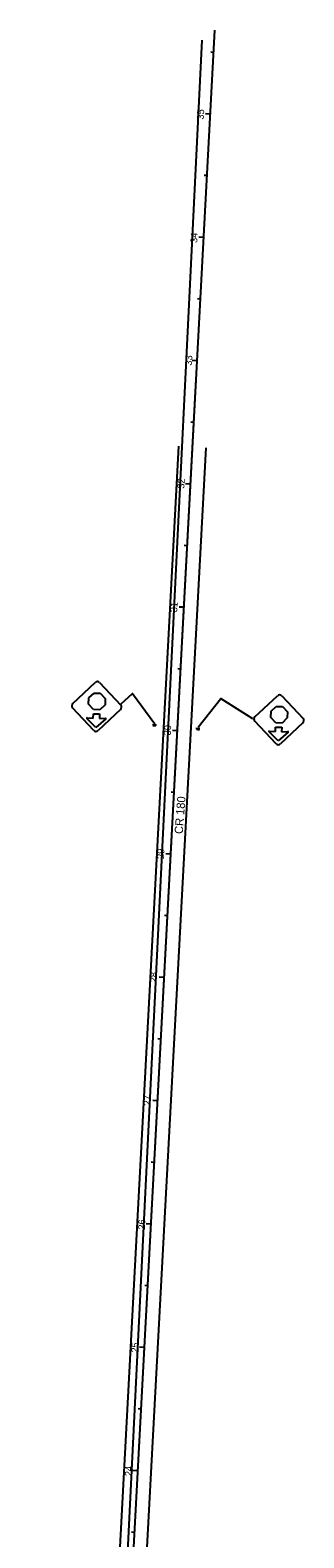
# Model space of a CAD drawing. Extents: x 1658454 to 1663955, y 480219 to 484109.
# Drawn here: x 1661328 to 1661550, y 482888 to 484109 of the extents above; entities that cross this region are included whole.
import ezdxf

# ---------------------------------------------------------------- set-up
doc = ezdxf.new("R2010")
doc.units = 0
for name, color, linetype in [('Default', 7, 'Continuous'), ('PM_P_CL_Double_Solid', 7, 'Continuous'), ('PV_P_EOP', 7, 'Continuous'), ('RW_X_CL_50', 7, 'Continuous'), ('SC_Scratch1', 7, 'Continuous'), ('SN_X_Public', 7, 'Continuous'), ('SV_X_CL_Survey_50', 7, 'Continuous'), ('SV_X_Text', 7, 'Continuous')]:
    doc.layers.add(name, color=color, linetype=linetype)

msp = doc.modelspace()

# ---------------------------------------------------------------- linework, layer by layer
at = {"layer": 'Default'}
for p, q in [((1661476.7, 484091), (1661474.3, 484091.1)), ((1661474, 484041.1), (1661470.1, 484041.3)), ((1661471.4, 483991.2), (1661469, 483991.3)), ((1661468.7, 483941.2), (1661464.7, 483941.4)), ((1661466, 483891.3), (1661463.6, 483891.4)), ((1661463.4, 483841.4), (1661459.4, 483841.6)), ((1661460.7, 483791.4), (1661458.3, 483791.6)), ((1661458, 483741.5), (1661454, 483741.7)), ((1661455.3, 483691.6), (1661452.9, 483691.7)), ((1661452.7, 483641.7), (1661448.7, 483641.9)), ((1661450, 483591.7), (1661447.6, 483591.9)), ((1661447.3, 483541.8), (1661443.3, 483542)), ((1661444.7, 483491.9), (1661442.3, 483492)), ((1661442, 483441.9), (1661438, 483442.2)), ((1661439.3, 483392), (1661436.9, 483392.1)), ((1661436.6, 483342.1), (1661432.6, 483342.3)), ((1661434, 483292.2), (1661431.6, 483292.3)), ((1661431.3, 483242.2), (1661427.3, 483242.4)), ((1661428.6, 483192.3), (1661426.2, 483192.4)), ((1661426, 483142.4), (1661422, 483142.6)), ((1661423.3, 483092.4), (1661420.9, 483092.6)), ((1661420.6, 483042.5), (1661416.6, 483042.7)), ((1661417.9, 482992.6), (1661415.5, 482992.7)), ((1661415.3, 482942.7), (1661411.3, 482942.9)), ((1661412.6, 482892.7), (1661410.2, 482892.9))]:
    msp.add_line(p, q, dxfattribs=at)
at = {"layer": 'PM_P_CL_Double_Solid'}
msp.add_line((1661344.5, 481619.5), (1661462.6, 483826.4), dxfattribs=at)
at = {"layer": 'PV_P_EOP'}
for p, q in [((1661398.1, 482828.2), (1661448.6, 483772.1)), ((1661420.1, 482827.1), (1661470.6, 483770.9))]:
    msp.add_line(p, q, dxfattribs=at)
at = {"layer": 'RW_X_CL_50'}
msp.add_line((1661341.7, 481544.6), (1661467.4, 484100.9), dxfattribs=at)
at = {"layer": 'SC_Scratch1'}
for p, q in [((1661375.5, 483568.3), (1661379.9, 483572.3)), ((1661379.9, 483572.3), (1661384.8, 483572.1)), ((1661384.8, 483572.1), (1661388.9, 483567.9)), ((1661375.4, 483563.2), (1661375.5, 483568.3)), ((1661379.5, 483558.9), (1661375.4, 483563.2)), ((1661384.4, 483558.8), (1661379.5, 483558.9)), ((1661388.8, 483562.8), (1661384.4, 483558.8)), ((1661388.9, 483567.9), (1661388.8, 483562.8)), ((1661522.9, 483552.5), (1661523.1, 483557.5)), ((1661523.1, 483557.5), (1661527.4, 483561.5)), ((1661527.4, 483561.5), (1661532.4, 483561.4)), ((1661532.4, 483561.4), (1661536.5, 483557.1)), ((1661536.5, 483557.1), (1661536.3, 483552.1)), ((1661381.4, 483544.3), (1661373.9, 483551.8)), ((1661374.2, 483552.3), (1661379.2, 483551.9)), ((1661379.2, 483551.9), (1661379.3, 483555.6)), ((1661379.3, 483555.6), (1661384.3, 483555.5)), ((1661389.4, 483551.3), (1661381.4, 483544.3)), ((1661384.3, 483555.5), (1661384.2, 483551.7)), ((1661384.2, 483551.7), (1661389.2, 483551.9)), ((1661527, 483548.2), (1661522.9, 483552.5)), ((1661526.7, 483541.1), (1661526.8, 483544.8)), ((1661526.8, 483544.8), (1661531.8, 483544.7)), ((1661532, 483548), (1661527, 483548.2)), ((1661531.8, 483544.7), (1661531.7, 483541)), ((1661536.3, 483552.1), (1661532, 483548)), ((1661529, 483533.5), (1661521.5, 483541)), ((1661521.7, 483541.5), (1661526.7, 483541.1)), ((1661536.9, 483540.6), (1661529, 483533.5)), ((1661531.7, 483541), (1661536.7, 483541.1))]:
    msp.add_line(p, q, dxfattribs=at)
for points in [[(1661362.6, 483563.7), (1661380.8, 483580.9)], [(1661384.3, 483580.8), (1661401.4, 483562.6)], [(1661401.7, 483563.5), (1661411.1, 483571.8), (1661429, 483547.4)], [(1661510.1, 483553), (1661528.3, 483570.1)], [(1661531.9, 483570), (1661549, 483551.8)], [(1661379.6, 483542), (1661362.5, 483560.2)], [(1661401.3, 483559.1), (1661383.1, 483541.9)], [(1661464.1, 483544.8), (1661482.4, 483567.8), (1661508.1, 483551.7)], [(1661527.2, 483531.3), (1661510, 483549.4)], [(1661548.9, 483548.3), (1661530.7, 483531.1)]]:
    msp.add_lwpolyline(points, dxfattribs=at)
for centre, radius, start, end in [((1661382.5, 483579.1), 2.5, 43.2993, 133.2993), ((1661530, 483568.3), 2.5, 43.2993, 133.2993), ((1661364.3, 483561.9), 2.5, 133.2993, 223.2993), ((1661399.6, 483560.9), 2.5, 313.2993, 43.2993), ((1661374.2, 483552), 0.313, 84.9085, 225.0923), ((1661389.2, 483551.5), 0.313, 311.5063, 91.6902), ((1661511.8, 483551.2), 2.5, 133.2993, 223.2993), ((1661547.2, 483550.1), 2.5, 313.2993, 43.2993), ((1661381.4, 483543.7), 2.5, 223.2993, 313.2993), ((1661521.7, 483541.2), 0.313, 84.9085, 225.0923), ((1661536.7, 483540.8), 0.313, 311.5063, 91.6902), ((1661529, 483533), 2.5, 223.2993, 313.2993)]:
    msp.add_arc(centre, radius, start, end, dxfattribs=at)
at = {"layer": 'SN_X_Public'}
for p, q in [((1661427.1, 483546.8), (1661430.3, 483546.6)), ((1661428.2, 483546.7), (1661428.1, 483545.1)), ((1661428.7, 483546.7), (1661428.7, 483546.7)), ((1661429.2, 483546.7), (1661429.1, 483545.1)), ((1661462.3, 483543.8), (1661465.5, 483543.6)), ((1661463.4, 483543.8), (1661463.3, 483542.2)), ((1661463.9, 483543.7), (1661463.9, 483543.7)), ((1661464.3, 483543.7), (1661464.3, 483542.1))]:
    msp.add_line(p, q, dxfattribs=at)
at = {"layer": 'SV_X_CL_Survey_50'}
msp.add_line((1661328.1, 481314.2), (1661477.7, 484109), dxfattribs=at)

# ---------------------------------------------------------------- texts
at = {"layer": 'SC_Scratch1'}
msp.add_text('CR 180', height=6.72, rotation=85.5385, dxfattribs=at).set_placement((1661451.6, 483458))
at = {"layer": 'SV_X_Text'}
for s, p in [('35', (1661468.6, 484036.5)), ('34', (1661463.4, 483936.6)), ('33', (1661459, 483837.3)), ('32', (1661452.9, 483737.6)), ('31', (1661447.1, 483637.6)), ('30', (1661441.9, 483537.9)), ('29', (1661436.4, 483437.8)), ('28', (1661430.5, 483337.9)), ('27', (1661425.5, 483238.2)), ('26', (1661421, 483137.7)), ('25', (1661415.5, 483038.1)), ('24', (1661410.4, 482938.1))]:
    msp.add_text(s, height=5.6, rotation=86.9368, dxfattribs=at).set_placement(p)

doc.saveas('drawing.dxf')
